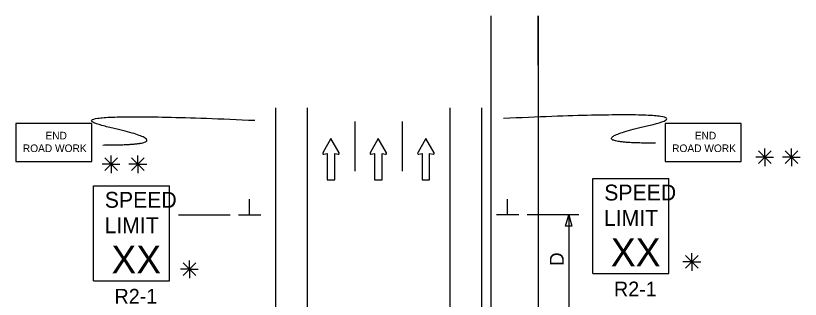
# Model space of a CAD drawing. Extents: x 16590 to 19508, y 5703 to 6974.
# Drawn here: x 16740.8 to 17137, y 6831.1 to 6974.1 of the extents above; entities that cross this region are included whole.
import ezdxf

# ---------------------------------------------------------------- set-up
doc = ezdxf.new("R2010")
doc.units = 0
for name, color, linetype in [('ALI_LEGAL_EX', 7, 'Continuous'), ('MT_SCRATCH_LEVEL_E', 7, 'Continuous'), ('PAVT_EDGE_EX', 7, 'Continuous'), ('TRAFFIC_SIGNS_PR', 7, 'Continuous'), ('TYPICAL_TEXT_DIMEN_PR', 7, 'Continuous')]:
    doc.layers.add(name, color=color, linetype=linetype)

msp = doc.modelspace()

# ---------------------------------------------------------------- linework, layer by layer
at = {"layer": 'ALI_LEGAL_EX'}
for p, q in [((16980.68, 6974.12), (16980.68, 6155.98)), ((17004.68, 6974.12), (17004.68, 6155.98)), ((16980.68, 6922.21), (16980.68, 6058.3)), ((17004.68, 6922.21), (17004.68, 6058.3))]:
    msp.add_line(p, q, dxfattribs=at)
for points in [[(17004.68, 6949.12), (17004.68, 6974.12)], [(16911.96, 6920.69), (16911.96, 6895.69)], [(16935.96, 6920.69), (16935.96, 6895.69)]]:
    msp.add_lwpolyline(points, dxfattribs=at)
at = {"layer": 'MT_SCRATCH_LEVEL_E'}
for p, q in [((16899.96, 6912.2), (16895.85, 6904.96)), ((16904.1, 6904.96), (16899.96, 6912.2)), ((16923.86, 6912.2), (16919.75, 6904.96)), ((16928.01, 6904.96), (16923.86, 6912.2)), ((16947.91, 6912.2), (16943.8, 6904.96)), ((16952.06, 6904.96), (16947.91, 6912.2)), ((16896.33, 6904.28), (16898.1, 6904.59)), ((16898.1, 6904.59), (16898.1, 6891.34)), ((16901.85, 6891.34), (16901.85, 6904.59)), ((16901.85, 6904.59), (16903.62, 6904.28)), ((16920.23, 6904.28), (16922.01, 6904.59)), ((16922.01, 6904.59), (16922.01, 6891.34)), ((16925.75, 6891.34), (16925.75, 6904.59)), ((16925.75, 6904.59), (16927.53, 6904.28)), ((16944.28, 6904.28), (16946.06, 6904.59)), ((16946.06, 6904.59), (16946.06, 6891.34)), ((16949.8, 6891.34), (16949.8, 6904.59)), ((16949.8, 6904.59), (16951.58, 6904.28)), ((16898.1, 6891.34), (16901.85, 6891.34)), ((16922.01, 6891.34), (16925.75, 6891.34)), ((16946.06, 6891.34), (16949.8, 6891.34))]:
    msp.add_line(p, q, dxfattribs=at)
for centre, start, end in [((16896.25, 6904.74), 150.4248, 279.9638), ((16903.69, 6904.74), 260.0362, 29.7731), ((16920.16, 6904.74), 150.4248, 279.9638), ((16927.6, 6904.74), 260.0362, 29.7731), ((16944.21, 6904.74), 150.4248, 279.9638), ((16951.65, 6904.74), 260.0362, 29.7731)]:
    msp.add_arc(centre, 0.463, start, end, dxfattribs=at)
at = {"layer": 'PAVT_EDGE_EX'}
for p, q in [((16871.96, 6927.73), (16871.96, 6245.87)), ((16887.96, 6927.73), (16887.96, 6245.87)), ((16959.96, 6927.73), (16959.96, 6245.87)), ((16975.96, 6927.73), (16975.96, 6245.87))]:
    msp.add_line(p, q, dxfattribs=at)
at = {"layer": 'TRAFFIC_SIGNS_PR'}
for p, q in [((17032.18, 6892.08), (17070.63, 6892.08)), ((17032.18, 6844.02), (17032.18, 6892.08)), ((17070.63, 6844.02), (17070.63, 6892.08)), ((16780, 6888.4), (16818.45, 6888.4)), ((16780, 6840.34), (16780, 6888.4)), ((16818.45, 6840.34), (16818.45, 6888.4)), ((17032.18, 6844.02), (17070.63, 6844.02)), ((16780, 6840.34), (16818.45, 6840.34))]:
    msp.add_line(p, q, dxfattribs=at)
for points in [[(16740.79, 6900.6), (16779.24, 6900.6), (16779.24, 6919.82), (16740.79, 6919.82)], [(17068.64, 6900.6), (17107.08, 6900.6), (17107.08, 6919.82), (17068.64, 6919.82)]]:
    msp.add_lwpolyline(points, close=True, dxfattribs=at)
for points in [[(16784.71, 6908.91), (16827.22, 6908.91), (16750.7, 6926.32), (16861.49, 6921.38)], [(17063.92, 6909.83), (17021.41, 6909.83), (17097.93, 6927.24), (16987.14, 6922.3)]]:
    msp.add_open_spline(points, degree=2, dxfattribs=at)
at = {"layer": 'TYPICAL_TEXT_DIMEN_PR'}
for p, q in [((17122.16, 6905.91), (17115.78, 6899.53)), ((17115.79, 6905.91), (17122.16, 6899.53)), ((17118.97, 6902.72), (17118.97, 6907.18)), ((17129.29, 6905.91), (17135.67, 6899.53)), ((17135.67, 6905.91), (17129.29, 6899.53)), ((17132.48, 6902.72), (17132.48, 6907.18)), ((16785.78, 6902.36), (16792.15, 6895.99)), ((16792.15, 6902.36), (16785.78, 6895.99)), ((16788.97, 6899.17), (16788.97, 6903.63)), ((16799.28, 6902.36), (16805.66, 6895.99)), ((16805.66, 6902.36), (16799.28, 6895.99)), ((16802.47, 6899.17), (16802.47, 6903.63)), ((17118.97, 6902.72), (17114.44, 6902.72)), ((17118.97, 6902.72), (17122.16, 6902.72)), ((17118.97, 6902.72), (17123.45, 6902.72)), ((17118.97, 6902.72), (17118.97, 6898.22)), ((17132.48, 6902.72), (17127.95, 6902.72)), ((17132.48, 6902.72), (17135.67, 6902.72)), ((17132.48, 6902.72), (17136.96, 6902.72)), ((17132.48, 6902.72), (17132.48, 6898.22)), ((16788.97, 6899.17), (16784.43, 6899.17)), ((16788.97, 6899.17), (16792.15, 6899.17)), ((16788.97, 6899.17), (16793.44, 6899.17)), ((16788.97, 6899.17), (16788.97, 6894.67)), ((16802.47, 6899.17), (16797.94, 6899.17)), ((16802.47, 6899.17), (16805.66, 6899.17)), ((16802.47, 6899.17), (16806.95, 6899.17)), ((16802.47, 6899.17), (16802.47, 6894.67)), ((16858.92, 6873.76), (16858.92, 6881.54)), ((16989.17, 6873.76), (16989.17, 6881.54)), ((16823.05, 6873.76), (16849.05, 6873.76)), ((16853.3, 6873.76), (16864.55, 6873.76)), ((16994.8, 6873.76), (16983.55, 6873.76)), ((17025.05, 6873.76), (16999.05, 6873.76)), ((17018.47, 6867.9), (17020.05, 6873.76)), ((17020.05, 6873.76), (17020.05, 6823.76)), ((17020.05, 6873.76), (17021.62, 6867.9)), ((17020.05, 6867.9), (17018.47, 6867.9)), ((17021.62, 6867.9), (17020.05, 6867.9)), ((17082.22, 6849.97), (17082.22, 6854.42)), ((16828.51, 6846.29), (16828.51, 6850.74)), ((17082.22, 6849.97), (17077.69, 6849.97)), ((17079.04, 6853.15), (17085.41, 6846.78)), ((17085.41, 6853.15), (17079.04, 6846.78)), ((17082.22, 6849.97), (17085.41, 6849.97)), ((17082.22, 6849.97), (17086.7, 6849.97)), ((17082.22, 6849.97), (17082.22, 6845.47)), ((16828.51, 6846.29), (16823.98, 6846.29)), ((16831.7, 6849.47), (16825.32, 6843.1)), ((16825.33, 6849.47), (16831.7, 6843.1)), ((16828.51, 6846.29), (16831.7, 6846.29)), ((16828.51, 6846.29), (16832.99, 6846.29)), ((16828.51, 6846.29), (16828.51, 6841.79))]:
    msp.add_line(p, q, dxfattribs=at)

# ---------------------------------------------------------------- texts
at = {"layer": 'TRAFFIC_SIGNS_PR'}
for s, height, p in [('END', 3.836, (16755.81, 6911.74)), ('END', 3.836, (17083.65, 6911.74)), ('ROAD WORK', 3.836, (16744.4, 6905.35)), ('ROAD WORK', 3.836, (17072.25, 6905.35)), ('SPEED', 8.01, (17037.95, 6880.93)), ('SPEED', 8.01, (16785.78, 6877.25)), ('LIMIT', 8.01, (17037.79, 6868.11)), ('LIMIT', 8.01, (16785.61, 6864.43)), ('XX', 14.048, (17041.3, 6847.78)), ('XX', 14.048, (16789.13, 6844.1)), ('R2-1', 7.449, (17042.87, 6832.56)), ('R2-1', 7.449, (16790.69, 6828.89))]:
    msp.add_text(s, height=height, dxfattribs=at).set_placement(p)
at = {"layer": 'TYPICAL_TEXT_DIMEN_PR'}
msp.add_text('D', height=7, rotation=90, dxfattribs=at).set_placement((17017.49, 6847.98))

doc.saveas('drawing.dxf')
